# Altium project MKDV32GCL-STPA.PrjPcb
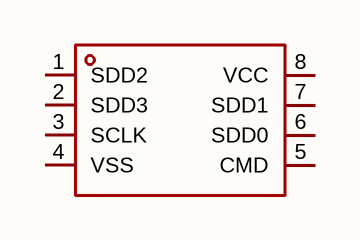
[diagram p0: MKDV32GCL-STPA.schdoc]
1 sheet, 1 parts. Net scope: global (net labels, ports and power ports of the same name join across sheets).

## Sheet MKDV32GCL-STPA.schdoc
size 127 x 101 mm

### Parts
U?  mkdv32gcl-stpa  [LGA-8_L8.0-W6.6-P1.27-TL-MKDV32GIL-STPB]  (value not drawn)

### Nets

Not connected (* = marked no-connect by the designer): U? 1(SDD2) 2(SDD3) 3(SCLK) 4(VSS) 5(CMD) 6(SDD0) 7(SDD1) 8(VCC)

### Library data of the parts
U? = mkdv32gcl-stpa: 存储容量:32Gbit;时钟频率(fc):50MHz;工作电压:2.7V~3.6V;; Manufacturer: MK(米客方德); AddInBom: yes; Memory Size: 32Gbit; Interface: SPI; Clock Frequency: 50MHz; Standby Supply Current: 190uA; Program / Erase Cycles: 5千次; ECC: 有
